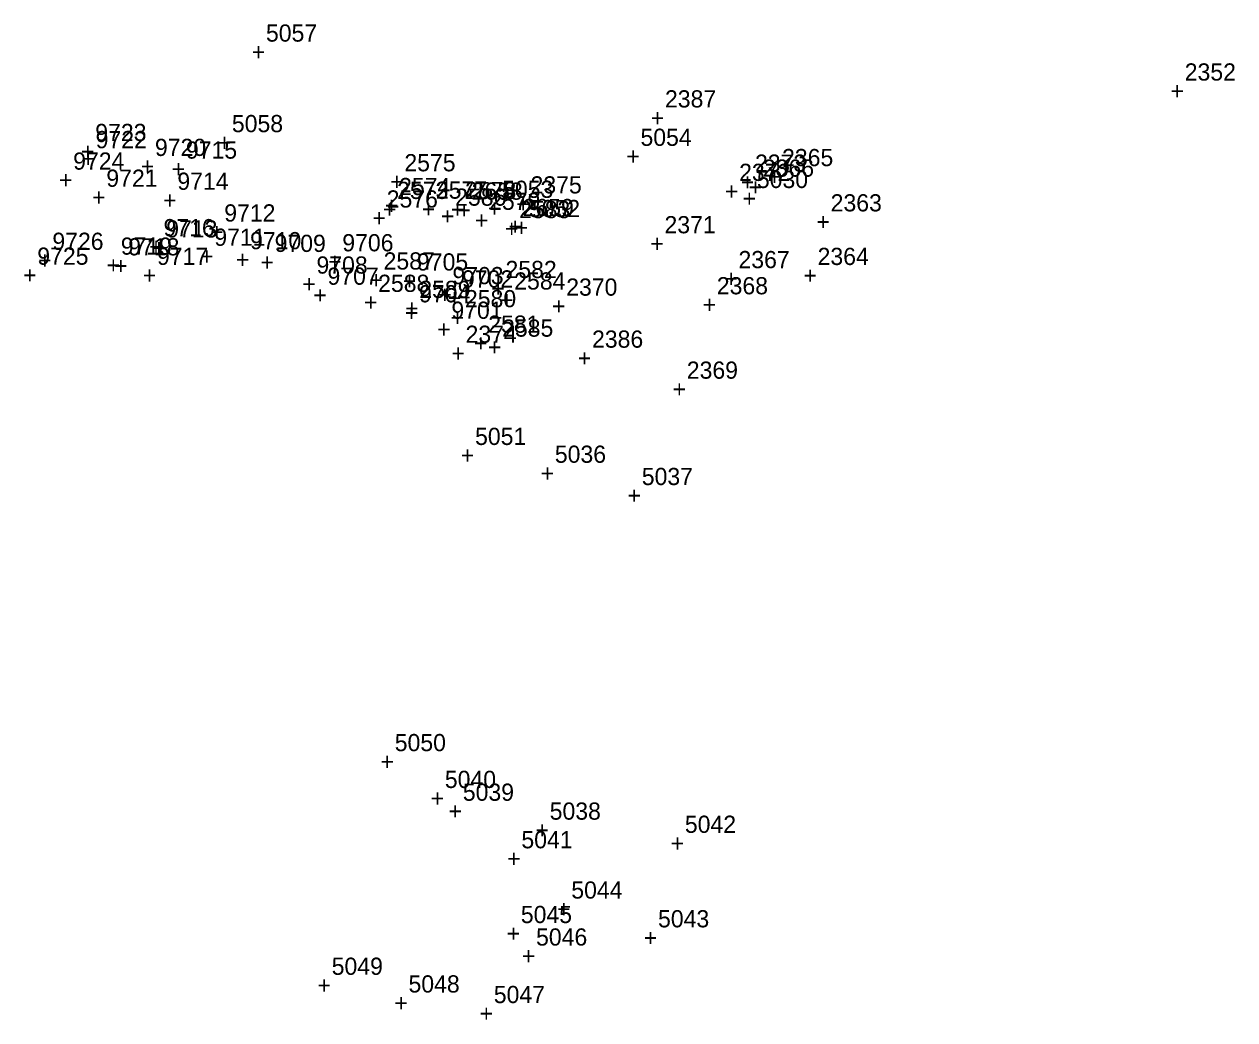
# Model space of a CAD drawing. Extents: x 1136220 to 1137808, y 528804 to 531215.
# Drawn here: x 1136788.5 to 1136964.3, y 529059.3 to 529204 of the extents above; entities that cross this region are included whole.
import ezdxf

# ---------------------------------------------------------------- set-up
doc = ezdxf.new("R2010")
doc.units = 0
for name, color, linetype in [('S_Buildings', 7, 'Continuous'), ('S_Buildings_Attachments', 7, 'Continuous'), ('S_Drainage_CB', 7, 'Continuous'), ('S_Drainage_Sump', 7, 'Continuous'), ('S_Ground_Elevation', 7, 'Continuous'), ('S_Ground_SpotElevation', 7, 'Continuous'), ('S_Property_Walkways', 7, 'Continuous'), ('S_Roadway_Centerline', 7, 'Continuous'), ('S_Roadway_Drive_Paved', 7, 'Continuous'), ('S_Roadway_Edge_Pavement', 7, 'Continuous'), ('S_Roadway_Painted_Lines', 7, 'Continuous'), ('S_Traffic_Sign_SinglePost', 7, 'Continuous'), ('S_Trees_Bush', 7, 'Continuous'), ('S_Utilities_Pole_Joint', 7, 'Continuous'), ('S_Utilities_UG_Gas_Line', 7, 'Continuous'), ('S_Utilities_UG_Sanitary_MH', 7, 'Continuous'), ('S_Utilities_UG_Telephone_MH', 7, 'Continuous'), ('S_Utilities_UG_Water_Gate', 7, 'Continuous')]:
    doc.layers.add(name, color=color, linetype=linetype)

msp = doc.modelspace()

# ---------------------------------------------------------------- texts
at = {"layer": 'S_Buildings'}
for s, p in [('2352', (1136957.06, 529195.78)), ('+', (1136955, 529193.03)), ('2363', (1136905.62, 529176.76)), ('+', (1136903.56, 529174.01))]:
    msp.add_text(s, height=2.5, dxfattribs=at).set_placement(p)
at = {"layer": 'S_Buildings_Attachments'}
for s, p in [('2364', (1136903.72, 529168.97)), ('+', (1136901.66, 529166.22))]:
    msp.add_text(s, height=2.5, dxfattribs=at).set_placement(p)
at = {"layer": 'S_Drainage_CB'}
for s, p in [('2573', (1136842.63, 529178.57)), ('+', (1136840.57, 529175.82)), ('5050', (1136842.29, 529098.3)), ('+', (1136840.23, 529095.55))]:
    msp.add_text(s, height=2.5, dxfattribs=at).set_placement(p)
at = {"layer": 'S_Drainage_Sump'}
for s, p in [('2574', (1136842.92, 529179.13)), ('+', (1136840.86, 529176.38))]:
    msp.add_text(s, height=2.5, dxfattribs=at).set_placement(p)
at = {"layer": 'S_Ground_Elevation'}
for s, p in [('9722', (1136798.84, 529185.95)), ('+', (1136796.78, 529183.2)), ('9714', (1136810.71, 529179.9)), ('+', (1136808.65, 529177.15)), ('9712', (1136817.52, 529175.29)), ('2583', (1136860.36, 529175.78)), ('9713', (1136809.09, 529172.97)), ('+', (1136815.46, 529172.54)), ('9711', (1136816.08, 529171.76)), ('+', (1136858.3, 529173.03)), ('9726', (1136792.55, 529171.17)), ('9719', (1136802.49, 529170.47)), ('+', (1136807.03, 529170.22)), ('9706', (1136834.67, 529170.96)), ('+', (1136790.49, 529168.42)), ('+', (1136814.02, 529169.01)), ('9705', (1136845.52, 529168.17)), ('+', (1136800.43, 529167.72)), ('9707', (1136832.52, 529166.1)), ('+', (1136832.61, 529168.21)), ('9703', (1136850.67, 529166.18)), ('2582', (1136858.38, 529167.07)), ('+', (1136843.46, 529165.42)), ('9702', (1136852.06, 529165.7)), ('2584', (1136859.65, 529165.4)), ('+', (1136830.46, 529163.35)), ('9704', (1136845.82, 529163.54)), ('+', (1136848.61, 529163.43)), ('+', (1136850, 529162.95)), ('+', (1136856.32, 529164.32)), ('9701', (1136850.52, 529161.15)), ('+', (1136857.59, 529162.65)), ('+', (1136843.76, 529160.79)), ('2581', (1136855.87, 529159.13)), ('+', (1136848.46, 529158.4)), ('2585', (1136857.89, 529158.55)), ('+', (1136853.81, 529156.38)), ('+', (1136855.83, 529155.8))]:
    msp.add_text(s, height=2.5, dxfattribs=at).set_placement(p)
at = {"layer": 'S_Ground_SpotElevation'}
for s, p in [('2575', (1136843.69, 529182.59)), ('+', (1136841.63, 529179.84)), ('2587', (1136840.67, 529168.31)), ('+', (1136838.6, 529165.56)), ('2588', (1136839.88, 529165.06)), ('2589', (1136845.86, 529164.18)), ('+', (1136837.82, 529162.31)), ('+', (1136843.8, 529161.43))]:
    msp.add_text(s, height=2.5, dxfattribs=at).set_placement(p)
at = {"layer": 'S_Property_Walkways'}
for s, p in [('9720', (1136807.45, 529184.82)), ('9715', (1136811.95, 529184.43)), ('+', (1136805.39, 529182.07)), ('+', (1136809.88, 529181.68)), ('2577', (1136848.27, 529178.61)), ('2578', (1136852.51, 529178.55)), ('2576', (1136841.12, 529177.32)), ('2579', (1136856, 529176.99)), ('+', (1136846.21, 529175.86)), ('+', (1136850.45, 529175.8)), ('9716', (1136808.7, 529173.15)), ('+', (1136839.06, 529174.57)), ('+', (1136853.94, 529174.24)), ('9718', (1136803.57, 529170.37)), ('+', (1136806.63, 529170.4)), ('9717', (1136807.75, 529168.99)), ('+', (1136801.51, 529167.62)), ('+', (1136805.68, 529166.24)), ('2580', (1136852.49, 529162.83)), ('+', (1136850.42, 529160.08))]:
    msp.add_text(s, height=2.5, dxfattribs=at).set_placement(p)
at = {"layer": 'S_Roadway_Centerline'}
for s, p in [('5057', (1136823.58, 529201.44)), ('+', (1136821.52, 529198.69)), ('2387', (1136881.55, 529191.87)), ('+', (1136879.49, 529189.12)), ('5054', (1136877.99, 529186.29)), ('+', (1136875.93, 529183.54)), ('2386', (1136870.95, 529156.95)), ('+', (1136868.89, 529154.2)), ('5036', (1136865.55, 529140.22)), ('+', (1136863.49, 529137.47)), ('5039', (1136852.18, 529091.09)), ('+', (1136850.11, 529088.34)), ('5048', (1136844.29, 529063.22)), ('+', (1136842.23, 529060.47))]:
    msp.add_text(s, height=2.5, dxfattribs=at).set_placement(p)
at = {"layer": 'S_Roadway_Drive_Paved'}
for s, p in [('9723', (1136798.78, 529186.99)), ('+', (1136796.71, 529184.24)), ('9724', (1136795.57, 529182.83)), ('+', (1136793.51, 529180.08)), ('9725', (1136790.36, 529169.01)), ('+', (1136788.3, 529166.26))]:
    msp.add_text(s, height=2.5, dxfattribs=at).set_placement(p)
at = {"layer": 'S_Roadway_Edge_Pavement'}
for s, p in [('5058', (1136818.63, 529188.28)), ('+', (1136816.57, 529185.53)), ('2365', (1136898.56, 529183.34)), ('5030', (1136894.9, 529180.16)), ('2366', (1136895.77, 529181.81)), ('+', (1136896.5, 529180.59)), ('5053', (1136857.89, 529178.73)), ('+', (1136893.71, 529179.06)), ('+', (1136892.83, 529177.41)), ('+', (1136855.83, 529175.98)), ('5052', (1136861.78, 529175.93)), ('+', (1136859.72, 529173.18)), ('2367', (1136892.23, 529168.51)), ('2368', (1136889.08, 529164.71)), ('+', (1136890.17, 529165.76)), ('+', (1136887.02, 529161.96)), ('2369', (1136884.72, 529152.44)), ('+', (1136882.66, 529149.69)), ('5051', (1136853.96, 529142.81)), ('+', (1136851.89, 529140.06)), ('5037', (1136878.18, 529136.98)), ('+', (1136876.12, 529134.23)), ('5038', (1136864.8, 529088.34)), ('+', (1136862.74, 529085.59)), ('5042', (1136884.44, 529086.43)), ('+', (1136882.38, 529083.68)), ('5044', (1136867.94, 529076.87)), ('5045', (1136860.61, 529073.31)), ('+', (1136865.88, 529074.12)), ('5043', (1136880.54, 529072.69)), ('+', (1136858.55, 529070.56)), ('+', (1136878.48, 529069.94)), ('5049', (1136833.13, 529065.79)), ('+', (1136831.07, 529063.04)), ('5047', (1136856.68, 529061.68)), ('+', (1136854.62, 529058.93))]:
    msp.add_text(s, height=2.5, dxfattribs=at).set_placement(p)
at = {"layer": 'S_Roadway_Painted_Lines'}
for s, p in [('2658', (1136853.45, 529178.46)), ('+', (1136851.39, 529175.71)), ('2659', (1136860.87, 529176.08)), ('+', (1136858.81, 529173.33))]:
    msp.add_text(s, height=2.5, dxfattribs=at).set_placement(p)
at = {"layer": 'S_Traffic_Sign_SinglePost'}
for s, p in [('2586', (1136851.07, 529177.59)), ('+', (1136849, 529174.84))]:
    msp.add_text(s, height=2.5, dxfattribs=at).set_placement(p)
at = {"layer": 'S_Trees_Bush'}
for s, p in [('9721', (1136800.39, 529180.34)), ('+', (1136798.33, 529177.59)), ('9710', (1136821.27, 529171.26)), ('9709', (1136824.84, 529170.87)), ('+', (1136819.21, 529168.51)), ('+', (1136822.78, 529168.12)), ('9708', (1136830.92, 529167.72)), ('+', (1136828.86, 529164.97))]:
    msp.add_text(s, height=2.5, dxfattribs=at).set_placement(p)
at = {"layer": 'S_Utilities_Pole_Joint'}
for s, p in [('5046', (1136862.82, 529070.04)), ('+', (1136860.76, 529067.29))]:
    msp.add_text(s, height=2.5, dxfattribs=at).set_placement(p)
at = {"layer": 'S_Utilities_UG_Gas_Line'}
for s, p in [('2375', (1136862.02, 529179.37)), ('+', (1136859.95, 529176.62)), ('2374', (1136852.58, 529157.66)), ('+', (1136850.52, 529154.91))]:
    msp.add_text(s, height=2.5, dxfattribs=at).set_placement(p)
at = {"layer": 'S_Utilities_UG_Sanitary_MH'}
for s, p in [('2372', (1136892.32, 529181.19)), ('+', (1136890.26, 529178.44)), ('5041', (1136860.69, 529084.18)), ('+', (1136858.63, 529081.43))]:
    msp.add_text(s, height=2.5, dxfattribs=at).set_placement(p)
at = {"layer": 'S_Utilities_UG_Telephone_MH'}
for s, p in [('2371', (1136881.48, 529173.58)), ('+', (1136879.42, 529170.83))]:
    msp.add_text(s, height=2.5, dxfattribs=at).set_placement(p)
at = {"layer": 'S_Utilities_UG_Water_Gate'}
for s, p in [('2373', (1136894.63, 529182.53)), ('+', (1136892.57, 529179.78)), ('2370', (1136867.2, 529164.51)), ('+', (1136865.14, 529161.76)), ('5040', (1136849.57, 529092.95)), ('+', (1136847.51, 529090.2))]:
    msp.add_text(s, height=2.5, dxfattribs=at).set_placement(p)

doc.saveas('drawing.dxf')
